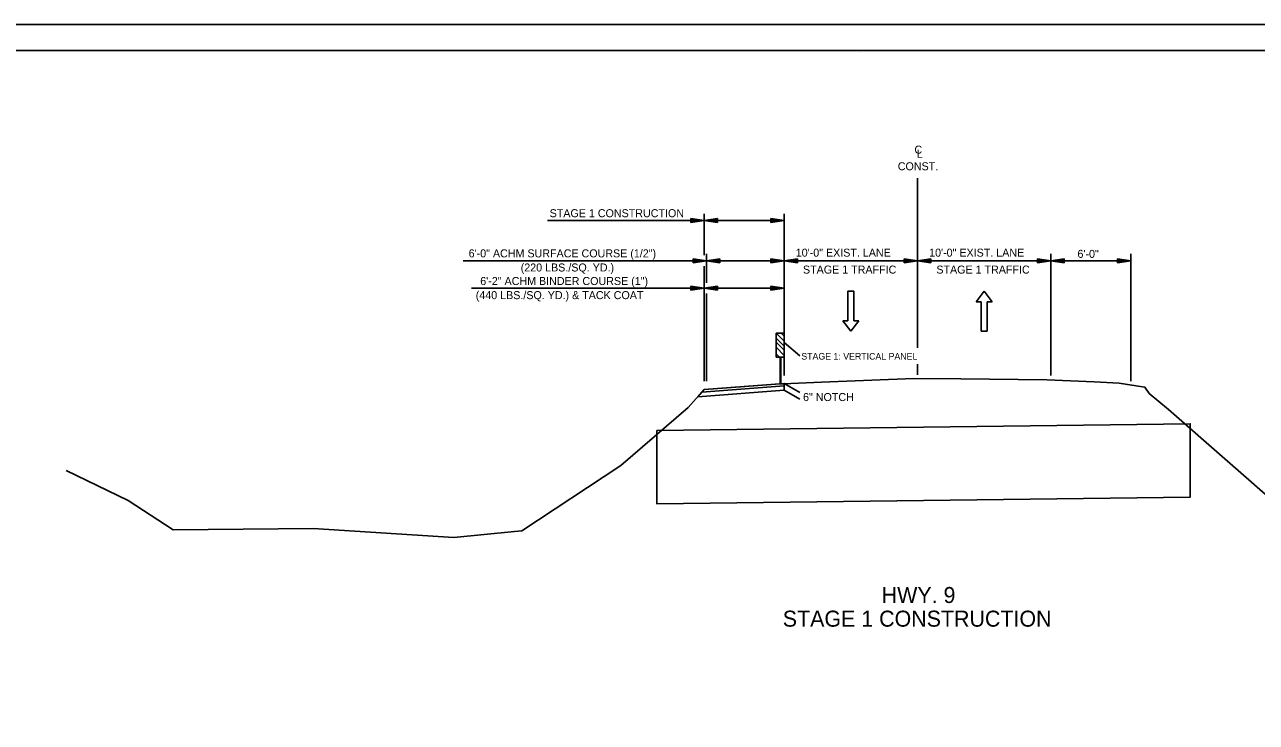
# Model space of a CAD drawing. Extents: x 1398460 to 1408037, y 380768 to 383968.
# Drawn here: x 1399197 to 1400121, y 383445 to 383968 of the extents above; entities that cross this region are included whole.
import ezdxf

# ---------------------------------------------------------------- set-up
doc = ezdxf.new("R2010")
doc.units = 0
for name, color, linetype in [('R_Border', 7, 'Continuous'), ('R_Dimension', 7, 'Continuous'), ('R_Draft', 7, 'Continuous'), ('R_Exist Surface', 7, 'Continuous'), ('R_MOT', 7, 'Continuous'), ('R_No Plot', 7, 'Continuous'), ('R_Striping', 7, 'Continuous'), ('R_Water', 7, 'Continuous')]:
    doc.layers.add(name, color=color, linetype=linetype)

msp = doc.modelspace()

# ---------------------------------------------------------------- linework, layer by layer
at = {"layer": 'R_Border'}
for p, q in [((1399060.87, 383948.11), (1400641.77, 383948.11)), ((1399823.47, 383946.81), (1399823.47, 383946.81)), ((1399823.47, 383946.81), (1399823.47, 383946.81))]:
    msp.add_line(p, q, dxfattribs=at)
at = {"layer": 'R_Dimension'}
for p, q in [((1399866.67, 383725.54), (1399866.67, 383852.48)), ((1399766.67, 383820.75), (1399589.29, 383820.75)), ((1399696.67, 383822.25), (1399706.67, 383820.75)), ((1399696.67, 383819.25), (1399696.67, 383822.25)), ((1399696.67, 383822), (1399705, 383820.75)), ((1399696.67, 383821.74), (1399703.28, 383820.75)), ((1399696.67, 383821.49), (1399701.61, 383820.75)), ((1399696.67, 383821.24), (1399699.92, 383820.75)), ((1399696.67, 383820.98), (1399698.25, 383820.75)), ((1399696.67, 383819.25), (1399706.67, 383820.75)), ((1399696.67, 383820.26), (1399699.92, 383820.75)), ((1399696.67, 383819.75), (1399703.28, 383820.75)), ((1399696.67, 383819.5), (1399705, 383820.75)), ((1399696.67, 383820), (1399701.61, 383820.75)), ((1399696.67, 383820.51), (1399698.25, 383820.75)), ((1399706.67, 383794.75), (1399706.67, 383825.75)), ((1399716.67, 383822.25), (1399706.67, 383820.75)), ((1399716.67, 383819.25), (1399706.67, 383820.75)), ((1399716.67, 383822), (1399708.34, 383820.75)), ((1399716.67, 383819.5), (1399708.34, 383820.75)), ((1399716.67, 383821.74), (1399710.06, 383820.75)), ((1399716.67, 383819.75), (1399710.06, 383820.75)), ((1399716.67, 383821.49), (1399711.72, 383820.75)), ((1399716.67, 383820), (1399711.72, 383820.75)), ((1399716.67, 383821.24), (1399713.42, 383820.75)), ((1399716.67, 383820.26), (1399713.42, 383820.75)), ((1399716.67, 383820.98), (1399715.09, 383820.75)), ((1399716.67, 383820.51), (1399715.09, 383820.75)), ((1399716.67, 383819.25), (1399716.67, 383822.25)), ((1399756.67, 383822.25), (1399766.67, 383820.75)), ((1399756.67, 383819.25), (1399756.67, 383822.25)), ((1399756.67, 383822), (1399765, 383820.75)), ((1399756.67, 383821.74), (1399763.28, 383820.75)), ((1399756.67, 383821.49), (1399761.61, 383820.75)), ((1399756.67, 383821.24), (1399759.92, 383820.75)), ((1399756.67, 383820.98), (1399758.25, 383820.75)), ((1399756.67, 383819.25), (1399766.67, 383820.75)), ((1399756.67, 383820.26), (1399759.92, 383820.75)), ((1399756.67, 383819.75), (1399763.28, 383820.75)), ((1399756.67, 383819.5), (1399765, 383820.75)), ((1399756.67, 383820), (1399761.61, 383820.75)), ((1399756.67, 383820.51), (1399758.25, 383820.75)), ((1399766.67, 383704.83), (1399766.67, 383825.75)), ((1399698.33, 383792.25), (1399708.33, 383790.75)), ((1399698.33, 383789.25), (1399698.33, 383792.25)), ((1399708.33, 383774.03), (1399708.33, 383795.75)), ((1399718.33, 383792.25), (1399708.33, 383790.75)), ((1399718.33, 383789.25), (1399718.33, 383792.25)), ((1399756.67, 383792.25), (1399766.67, 383790.75)), ((1399756.67, 383789.25), (1399756.67, 383792.25)), ((1399776.67, 383792.25), (1399766.67, 383790.75)), ((1399776.67, 383789.25), (1399776.67, 383792.25)), ((1399856.67, 383792.25), (1399866.67, 383790.75)), ((1399856.67, 383789.25), (1399856.67, 383792.25)), ((1399876.67, 383792.25), (1399866.67, 383790.75)), ((1399876.67, 383789.25), (1399876.67, 383792.25)), ((1399956.67, 383792.25), (1399966.67, 383790.75)), ((1399956.67, 383789.25), (1399956.67, 383792.25)), ((1399966.67, 383704.83), (1399966.67, 383795.75)), ((1399976.67, 383792.25), (1399966.67, 383790.75)), ((1399976.67, 383789.25), (1399976.67, 383792.25)), ((1400016.67, 383792.25), (1400026.67, 383790.75)), ((1400016.67, 383789.25), (1400016.67, 383792.25)), ((1400026.67, 383700.4), (1400026.67, 383795.75)), ((1399526.02, 383790.75), (1399766.67, 383790.75)), ((1399698.33, 383792), (1399706.66, 383790.75)), ((1399698.33, 383791.74), (1399704.94, 383790.75)), ((1399698.33, 383791.49), (1399703.28, 383790.75)), ((1399698.33, 383791.24), (1399701.58, 383790.75)), ((1399698.33, 383790.98), (1399699.91, 383790.75)), ((1399698.33, 383789.25), (1399708.33, 383790.75)), ((1399698.33, 383790.26), (1399701.58, 383790.75)), ((1399698.33, 383789.75), (1399704.94, 383790.75)), ((1399698.33, 383789.5), (1399706.66, 383790.75)), ((1399698.33, 383790), (1399703.28, 383790.75)), ((1399698.33, 383790.51), (1399699.91, 383790.75)), ((1399706.67, 383700.4), (1399706.67, 383786.75)), ((1399718.33, 383789.25), (1399708.33, 383790.75)), ((1399718.33, 383792), (1399710, 383790.75)), ((1399718.33, 383789.5), (1399710, 383790.75)), ((1399718.33, 383791.74), (1399711.72, 383790.75)), ((1399718.33, 383789.75), (1399711.72, 383790.75)), ((1399718.33, 383791.49), (1399713.39, 383790.75)), ((1399718.33, 383790), (1399713.39, 383790.75)), ((1399718.33, 383791.24), (1399715.08, 383790.75)), ((1399718.33, 383790.26), (1399715.08, 383790.75)), ((1399718.33, 383790.98), (1399716.75, 383790.75)), ((1399718.33, 383790.51), (1399716.75, 383790.75)), ((1399756.67, 383792), (1399765, 383790.75)), ((1399756.67, 383791.74), (1399763.28, 383790.75)), ((1399756.67, 383791.49), (1399761.61, 383790.75)), ((1399756.67, 383791.24), (1399759.92, 383790.75)), ((1399756.67, 383790.98), (1399758.25, 383790.75)), ((1399756.67, 383789.25), (1399766.67, 383790.75)), ((1399756.67, 383790.26), (1399759.92, 383790.75)), ((1399756.67, 383789.75), (1399763.28, 383790.75)), ((1399756.67, 383789.5), (1399765, 383790.75)), ((1399756.67, 383790), (1399761.61, 383790.75)), ((1399756.67, 383790.51), (1399758.25, 383790.75)), ((1399866.67, 383790.75), (1399766.67, 383790.75)), ((1399776.67, 383789.25), (1399766.67, 383790.75)), ((1399776.67, 383792), (1399768.34, 383790.75)), ((1399776.67, 383789.5), (1399768.34, 383790.75)), ((1399776.67, 383791.74), (1399770.06, 383790.75)), ((1399776.67, 383789.75), (1399770.06, 383790.75)), ((1399776.67, 383791.49), (1399771.72, 383790.75)), ((1399776.67, 383790), (1399771.72, 383790.75)), ((1399776.67, 383791.24), (1399773.42, 383790.75)), ((1399776.67, 383790.26), (1399773.42, 383790.75)), ((1399776.67, 383790.98), (1399775.09, 383790.75)), ((1399776.67, 383790.51), (1399775.09, 383790.75)), ((1399856.67, 383792), (1399865, 383790.75)), ((1399856.67, 383791.74), (1399863.28, 383790.75)), ((1399856.67, 383791.49), (1399861.61, 383790.75)), ((1399856.67, 383791.24), (1399859.92, 383790.75)), ((1399856.67, 383790.98), (1399858.25, 383790.75)), ((1399856.67, 383789.25), (1399866.67, 383790.75)), ((1399856.67, 383790.26), (1399859.92, 383790.75)), ((1399856.67, 383789.75), (1399863.28, 383790.75)), ((1399856.67, 383789.5), (1399865, 383790.75)), ((1399856.67, 383790), (1399861.61, 383790.75)), ((1399856.67, 383790.51), (1399858.25, 383790.75)), ((1399966.67, 383790.75), (1399866.67, 383790.75)), ((1399876.67, 383789.25), (1399866.67, 383790.75)), ((1399876.67, 383792), (1399868.34, 383790.75)), ((1399876.67, 383789.5), (1399868.34, 383790.75)), ((1399876.67, 383791.74), (1399870.06, 383790.75)), ((1399876.67, 383789.75), (1399870.06, 383790.75)), ((1399876.67, 383791.49), (1399871.72, 383790.75)), ((1399876.67, 383790), (1399871.72, 383790.75)), ((1399876.67, 383791.24), (1399873.42, 383790.75)), ((1399876.67, 383790.26), (1399873.42, 383790.75)), ((1399876.67, 383790.98), (1399875.09, 383790.75)), ((1399876.67, 383790.51), (1399875.09, 383790.75)), ((1399956.67, 383792), (1399965, 383790.75)), ((1399956.67, 383791.74), (1399963.28, 383790.75)), ((1399956.67, 383791.49), (1399961.61, 383790.75)), ((1399956.67, 383791.24), (1399959.92, 383790.75)), ((1399956.67, 383790.98), (1399958.25, 383790.75)), ((1399956.67, 383789.25), (1399966.67, 383790.75)), ((1399956.67, 383790.26), (1399959.92, 383790.75)), ((1399956.67, 383789.75), (1399963.28, 383790.75)), ((1399956.67, 383789.5), (1399965, 383790.75)), ((1399956.67, 383790), (1399961.61, 383790.75)), ((1399956.67, 383790.51), (1399958.25, 383790.75)), ((1399976.67, 383789.25), (1399966.67, 383790.75)), ((1399966.67, 383790.75), (1400026.67, 383790.75)), ((1399976.67, 383792), (1399968.34, 383790.75)), ((1399976.67, 383789.5), (1399968.34, 383790.75)), ((1399976.67, 383791.74), (1399970.06, 383790.75)), ((1399976.67, 383789.75), (1399970.06, 383790.75)), ((1399976.67, 383791.49), (1399971.72, 383790.75)), ((1399976.67, 383790), (1399971.72, 383790.75)), ((1399976.67, 383791.24), (1399973.42, 383790.75)), ((1399976.67, 383790.26), (1399973.42, 383790.75)), ((1399976.67, 383790.98), (1399975.09, 383790.75)), ((1399976.67, 383790.51), (1399975.09, 383790.75)), ((1400016.67, 383792), (1400025, 383790.75)), ((1400016.67, 383791.74), (1400023.28, 383790.75)), ((1400016.67, 383791.49), (1400021.61, 383790.75)), ((1400016.67, 383791.24), (1400019.92, 383790.75)), ((1400016.67, 383790.98), (1400018.25, 383790.75)), ((1400016.67, 383789.25), (1400026.67, 383790.75)), ((1400016.67, 383790.26), (1400019.92, 383790.75)), ((1400016.67, 383789.75), (1400023.28, 383790.75)), ((1400016.67, 383789.5), (1400025, 383790.75)), ((1400016.67, 383790), (1400021.61, 383790.75)), ((1400016.67, 383790.51), (1400018.25, 383790.75)), ((1399532.31, 383770.03), (1399766.67, 383770.03)), ((1399696.67, 383771.53), (1399706.67, 383770.03)), ((1399696.67, 383768.53), (1399696.67, 383771.53)), ((1399696.67, 383771.28), (1399705, 383770.03)), ((1399696.67, 383771.03), (1399703.28, 383770.03)), ((1399696.67, 383770.78), (1399701.61, 383770.03)), ((1399696.67, 383770.52), (1399699.92, 383770.03)), ((1399696.67, 383770.27), (1399698.25, 383770.03)), ((1399696.67, 383768.53), (1399706.67, 383770.03)), ((1399696.67, 383769.55), (1399699.92, 383770.03)), ((1399696.67, 383769.04), (1399703.28, 383770.03)), ((1399696.67, 383768.78), (1399705, 383770.03)), ((1399696.67, 383769.29), (1399701.61, 383770.03)), ((1399696.67, 383769.8), (1399698.25, 383770.03)), ((1399716.67, 383771.53), (1399706.67, 383770.03)), ((1399716.67, 383768.53), (1399706.67, 383770.03)), ((1399708.33, 383700.4), (1399708.33, 383766.03)), ((1399716.67, 383771.28), (1399708.34, 383770.03)), ((1399716.67, 383768.78), (1399708.34, 383770.03)), ((1399716.67, 383771.03), (1399710.06, 383770.03)), ((1399716.67, 383769.04), (1399710.06, 383770.03)), ((1399716.67, 383770.78), (1399711.72, 383770.03)), ((1399716.67, 383769.29), (1399711.72, 383770.03)), ((1399716.67, 383770.52), (1399713.42, 383770.03)), ((1399716.67, 383769.55), (1399713.42, 383770.03)), ((1399716.67, 383770.27), (1399715.09, 383770.03)), ((1399716.67, 383769.8), (1399715.09, 383770.03)), ((1399716.67, 383768.53), (1399716.67, 383771.53)), ((1399756.67, 383771.53), (1399766.67, 383770.03)), ((1399756.67, 383768.53), (1399756.67, 383771.53)), ((1399756.67, 383771.28), (1399765, 383770.03)), ((1399756.67, 383771.03), (1399763.28, 383770.03)), ((1399756.67, 383770.78), (1399761.61, 383770.03)), ((1399756.67, 383770.52), (1399759.92, 383770.03)), ((1399756.67, 383770.27), (1399758.25, 383770.03)), ((1399756.67, 383768.53), (1399766.67, 383770.03)), ((1399756.67, 383769.55), (1399759.92, 383770.03)), ((1399756.67, 383769.04), (1399763.28, 383770.03)), ((1399756.67, 383768.78), (1399765, 383770.03)), ((1399756.67, 383769.29), (1399761.61, 383770.03)), ((1399756.67, 383769.8), (1399758.25, 383770.03)), ((1399766.67, 383729.46), (1399778.39, 383719.43)), ((1399866.67, 383705.1), (1399866.67, 383713.1)), ((1399706.64, 383694.16), (1399701.84, 383688.8)), ((1399766.67, 383693.66), (1399701.84, 383688.8)), ((1399766.67, 383696.96), (1399705.01, 383692.34)), ((1399766.67, 383698.66), (1399706.64, 383694.16))]:
    msp.add_line(p, q, dxfattribs=at)
for points in [[(1399766.67, 383696.96), (1399766.67, 383693.66), (1399701.84, 383688.8), (1399705.01, 383692.34)], [(1399766.67, 383698.66), (1399706.64, 383694.16), (1399705.01, 383692.34), (1399766.67, 383696.96)]]:
    msp.add_lwpolyline(points, close=True, dxfattribs=at)
for points in [[(1399705.01, 383692.34), (1399701.84, 383688.8), (1399766.67, 383693.66), (1399766.67, 383696.96), (1399705.01, 383692.34)], [(1399766.67, 383698.66), (1399706.64, 383694.16), (1399705.01, 383692.34), (1399766.67, 383696.96), (1399766.67, 383698.66)]]:
    msp.add_lwpolyline(points, dxfattribs=at)
at = {"layer": 'R_Draft'}
for p, q in [((1399766.67, 383698.66), (1399778.28, 383691.95)), ((1399766.67, 383693.66), (1399778.28, 383686.95))]:
    msp.add_line(p, q, dxfattribs=at)
at = {"layer": 'R_Exist Surface'}
msp.add_lwpolyline([(1399228.4, 383633.57), (1399274.79, 383611.15), (1399308.64, 383589), (1399413.54, 383589.98), (1399518.92, 383583.23), (1399564.54, 383587.94), (1399570.04, 383588.45), (1399644.13, 383637.35), (1399694.66, 383680.83), (1399706.58, 383694.15), (1399724, 383695.45), (1399760.08, 383698.29), (1399794.58, 383699.71), (1399863.93, 383702.38), (1399899.16, 383702.19), (1399963.63, 383701.46), (1399999.02, 383699.85), (1400017.72, 383699), (1400035.29, 383696.23), (1400037.12, 383695.86), (1400040.35, 383691.29), (1400054.83, 383679.16), (1400141.21, 383603.56)], dxfattribs=at)
at = {"layer": 'R_MOT'}
for p, q in [((1399764.44, 383736.45), (1399760.63, 383736.45)), ((1399766.67, 383730.45), (1399760.63, 383736.45)), ((1399760.63, 383720.83), (1399760.63, 383736.45)), ((1399760.63, 383732.66), (1399766.67, 383726.66)), ((1399760.63, 383729.59), (1399766.67, 383723.58)), ((1399760.63, 383725.84), (1399760.63, 383729.59)), ((1399766.67, 383736.45), (1399764.44, 383736.45)), ((1399764.44, 383736.45), (1399766.67, 383734.26)), ((1399766.67, 383734.26), (1399766.67, 383736.45)), ((1399766.67, 383718.4), (1399766.67, 383734.26)), ((1399766.67, 383726.66), (1399766.67, 383730.45)), ((1399766.67, 383719.82), (1399760.63, 383725.84)), ((1399763.07, 383718.4), (1399760.63, 383720.83)), ((1399760.63, 383720.83), (1399760.63, 383718.4)), ((1399760.63, 383718.4), (1399763.07, 383718.4)), ((1399766.67, 383718.4), (1399763.07, 383718.4)), ((1399763.66, 383698.47), (1399763.66, 383718.24)), ((1399764.13, 383698.47), (1399764.13, 383718.24))]:
    msp.add_line(p, q, dxfattribs=at)
at = {"layer": 'R_No Plot'}
msp.add_line((1398998.86, 383967.58), (1400665.53, 383967.58), dxfattribs=at)
for points in [[(1398998.83, 383967.58), (1400665.53, 383967.58), (1400665.53, 382900.89), (1398998.83, 382900.89)], [(1400230.47, 383948.11), (1400328.57, 383948.11), (1400328.57, 383898.71), (1400409.13, 383898.71), (1400525.12, 383898.71), (1400525.12, 383777.04), (1400641.77, 383777.04), (1400641.77, 382920.81), (1399060.87, 382920.81), (1399060.87, 383948.11)]]:
    msp.add_lwpolyline(points, close=True, dxfattribs=at)
at = {"layer": 'R_Striping'}
for p, q in [((1399814.42, 383745.75), (1399814.42, 383767.81)), ((1399818.92, 383767.81), (1399814.42, 383767.81)), ((1399818.92, 383745.75), (1399818.92, 383767.81)), ((1399910.67, 383760.03), (1399916.67, 383767.81)), ((1399916.67, 383767.81), (1399922.67, 383760.03)), ((1399910.67, 383760.03), (1399914.42, 383760.03)), ((1399914.42, 383760.03), (1399914.42, 383737.96)), ((1399918.92, 383760.03), (1399918.92, 383737.96)), ((1399918.92, 383760.03), (1399922.67, 383760.03)), ((1399814.42, 383745.75), (1399810.67, 383745.75)), ((1399816.67, 383737.96), (1399810.67, 383745.75)), ((1399822.67, 383745.75), (1399816.67, 383737.96)), ((1399822.67, 383745.75), (1399818.92, 383745.75)), ((1399914.42, 383737.96), (1399918.92, 383737.96))]:
    msp.add_line(p, q, dxfattribs=at)
at = {"layer": 'R_Water'}
msp.add_lwpolyline([(1399671.14, 383663.59), (1400071.14, 383668.59), (1400071.14, 383613.59), (1399671.14, 383608.59)], close=True, dxfattribs=at)

# ---------------------------------------------------------------- texts
at = {"layer": 'R_Dimension'}
for s, p in [('C', (1399864.32, 383870.92)), ('L', (1399866.12, 383867.87)), ('CONST.', (1399851.83, 383858.48)), ('STAGE 1 CONSTRUCTION', (1399590.82, 383823.31)), ('6\'-0" ACHM SURFACE COURSE (1/2")', (1399530.11, 383793.22)), ('10\'-0" EXIST. LANE', (1399775.34, 383793.75)), ('10\'-0" EXIST. LANE', (1399875.34, 383793.75)), ('6\'-0"', (1399986.54, 383792.85)), ('(220 LBS./SQ. YD.)', (1399569.13, 383782.64)), ('STAGE 1 TRAFFIC', (1399780.75, 383781.07)), ('STAGE 1 TRAFFIC', (1399880.75, 383781.07)), ('6\'-2" ACHM BINDER COURSE (1")', (1399538.8, 383772.5)), ('(440 LBS./SQ. YD.) & TACK COAT', (1399535.42, 383761.93)), ('6" NOTCH', (1399780.81, 383685.57))]:
    msp.add_text(s, height=6, dxfattribs=at).set_placement(p)
at = {"layer": 'R_Draft'}
for s, height, p in [('STAGE 1: VERTICAL PANEL', 4.9184, (1399779.51, 383716.64)), ('HWY. 9', 12, (1399839.78, 383534.26)), ('STAGE 1 CONSTRUCTION', 12, (1399765.61, 383516.54))]:
    msp.add_text(s, height=height, dxfattribs=at).set_placement(p)

doc.saveas('drawing.dxf')
